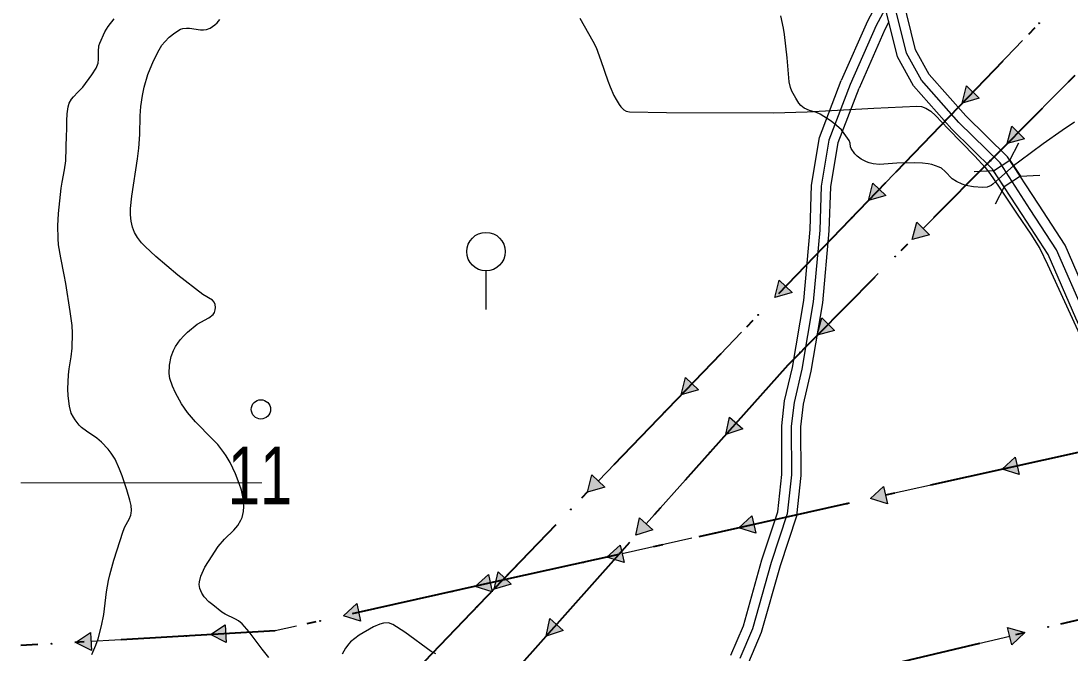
# Model space of a CAD drawing. Extents: x -64005 to -55000, y -89025 to -80000.
# Drawn here: x -64000 to -62912, y -85176 to -84521 of the extents above; entities that cross this region are included whole.
import ezdxf
from ezdxf.enums import TextEntityAlignment as Align

# ---------------------------------------------------------------- set-up
doc = ezdxf.new("R2010")
doc.units = 0
doc.header["$LTSCALE"] = 32
for name, pattern in [('DASH_DOUBLE_DOT', [9.2, 5, -1.2, 0.3, -1.2, 0.3, -1.2]), ('DOT_DASHED', [7.7, 5, -1.2, 0.3, -1.2]), ('LONG_DASHED', [7.5, 6, -1.5])]:
    doc.linetypes.add(name, pattern=pattern)
for name, color, linetype, lineweight in [('18', 7, 'Continuous', 25), ('2', 7, 'Continuous', 25), ('20', 7, 'Continuous', 25), ('24', 7, 'Continuous', 25), ('32', 7, 'Continuous', 25), ('35', 7, 'Continuous', 13), ('39', 7, 'LONG_DASHED', 25), ('52', 7, 'Continuous', 25), ('6', 7, 'Continuous', 25), ('63', 7, 'DASH_DOUBLE_DOT', 25), ('8', 7, 'Continuous', 25)]:
    doc.layers.add(name, color=color, linetype=linetype, lineweight=lineweight)
doc.layers.add('38', color=7, linetype='Continuous')

msp = doc.modelspace()

# ---------------------------------------------------------------- hatches: boundary and pattern name
at = {"layer": '18'}
for points in [[(-63005.72, -84601.15), (-63023.5, -84606.26), (-63019.04, -84588.31)], [(-62958.84, -84643.33), (-62976.69, -84648.19), (-62971.97, -84630.3)], [(-63102.86, -84701.96), (-63120.64, -84707.07), (-63116.19, -84689.12)], [(-63057.45, -84742.71), (-63075.3, -84747.56), (-63070.58, -84729.68)], [(-63200.01, -84802.77), (-63217.79, -84807.88), (-63213.33, -84789.93)], [(-63156.07, -84842.08), (-63173.92, -84846.94), (-63169.2, -84829.05)], [(-63297.15, -84903.58), (-63314.93, -84908.7), (-63310.48, -84890.74)], [(-63251.2, -84944.05), (-63268.77, -84949.85), (-63265.01, -84931.74)], [(-62964.36, -84991.49), (-62982, -84985.94), (-62968.37, -84973.43)], [(-63394.3, -85004.39), (-63412.08, -85009.51), (-63407.62, -84991.55)], [(-63101.03, -85021.85), (-63118.67, -85016.3), (-63105.04, -85003.8)], [(-63237.69, -85052.22), (-63255.34, -85046.66), (-63241.71, -85034.16)], [(-63344.36, -85048.55), (-63361.93, -85054.35), (-63358.17, -85036.24)], [(-63374.36, -85082.58), (-63392.01, -85077.02), (-63378.37, -85064.52)], [(-63511.03, -85112.94), (-63528.68, -85107.38), (-63515.04, -85094.88)], [(-63491.44, -85105.2), (-63509.22, -85110.32), (-63504.77, -85092.36)], [(-63647.7, -85143.3), (-63665.34, -85137.74), (-63651.71, -85125.24)], [(-63437.52, -85153.06), (-63455.09, -85158.86), (-63451.33, -85140.75)], [(-63926.75, -85173.71), (-63943.27, -85165.39), (-63927.81, -85155.24)], [(-63786.98, -85165.7), (-63803.5, -85157.38), (-63788.04, -85147.23)], [(-62976.32, -85149.86), (-62958.61, -85155.18), (-62972.07, -85167.87)]]:
    msp.add_hatch(color=256, dxfattribs=at).paths.add_polyline_path(points)

# ---------------------------------------------------------------- linework, layer by layer
for p, q in [((-62961.05, -84541.46), (-63012.38, -84594.73)), ((-62913.29, -84584.31), (-62965.4, -84636.82)), ((-63011.91, -84683.68), (-63064.02, -84736.19)), ((-63155.34, -84743.08), (-63206.67, -84796.35)), ((-63110.52, -84783.06), (-63162.63, -84835.57)), ((-63252.48, -84843.89), (-63303.81, -84897.16)), ((-63208.88, -84882.67), (-63258.11, -84937.89)), ((-63349.63, -84944.7), (-63400.96, -84997.97)), ((-62894.14, -84966.42), (-62966.36, -84982.46)), ((-63302.04, -84987.17), (-63351.27, -85042.4)), ((-63030.81, -84996.78), (-63103.03, -85012.83)), ((-63167.48, -85027.14), (-63239.7, -85043.19)), ((-63446.77, -85045.51), (-63498.11, -85098.78)), ((-63304.15, -85057.51), (-63376.37, -85073.55)), ((-63395.2, -85091.68), (-63444.43, -85146.9)), ((-63577.49, -85118.22), (-63649.7, -85134.27)), ((-63543.92, -85146.32), (-63595.25, -85199.59)), ((-63853.42, -85160.24), (-63927.28, -85164.48)), ((-63046.2, -85175.86), (-62974.2, -85158.86)), ((-63993.19, -85168.26), (-64000, -85168.65))]:
    msp.add_line(p, q, dxfattribs=at)
at = {"layer": '18', "linetype": 'DOT_DASHED', "lineweight": 40}
for points in [[(-55000.81, -81341.27), (-57492.65, -83191.85), (-58506.34, -83610.82), (-59176.97, -83888), (-59245.7, -83916.4), (-60498.5, -84434.2), (-61697.45, -84700.56), (-63379.7, -85074.29), (-63500.32, -85101.08), (-63736.4, -85153.53), (-64000, -85168.65)], [(-62369.26, -83445.65), (-62236.29, -83546.11), (-62227.39, -83552.83), (-62158.46, -83621.75), (-62183.05, -83848.43), (-62289.57, -83955.78), (-62419.8, -84087.01), (-63204.55, -84877.81), (-63379.7, -85074.29), (-63583.22, -85302.6), (-63848.56, -85600.24), (-64000, -85590.13)], [(-62600.64, -83578.59), (-62627.36, -83673.57), (-62637.7, -84129.6), (-62639.47, -84207.74), (-63103.07, -84688.84), (-63500.32, -85101.08), (-63677.61, -85285.06), (-63756.78, -85343.55), (-64000, -85523.25)], [(-64000, -85400.95), (-63756.78, -85343.55), (-63583.22, -85302.6), (-63160.94, -85202.94), (-62774.07, -85111.63), (-62063.05, -84888.71), (-61746.39, -84828.12), (-61731.7, -84825.31), (-61594.06, -84786.87), (-61360.14, -84721.55), (-60481.8, -84478.68), (-59562.86, -84105.04), (-59208.4, -83960.92), (-58840.52, -84105.61)]]:
    msp.add_lwpolyline(points, dxfattribs=at)
at = {"layer": '18'}
for points in [[(-63005.72, -84601.15), (-63023.5, -84606.26), (-63019.04, -84588.31)], [(-62958.84, -84643.33), (-62976.69, -84648.19), (-62971.97, -84630.3)], [(-63102.86, -84701.96), (-63120.64, -84707.07), (-63116.19, -84689.12)], [(-63057.45, -84742.71), (-63075.3, -84747.56), (-63070.58, -84729.68)], [(-63200.01, -84802.77), (-63217.79, -84807.88), (-63213.33, -84789.93)], [(-63156.07, -84842.08), (-63173.92, -84846.94), (-63169.2, -84829.05)], [(-63297.15, -84903.58), (-63314.93, -84908.7), (-63310.48, -84890.74)], [(-63251.2, -84944.05), (-63268.77, -84949.85), (-63265.01, -84931.74)], [(-62964.36, -84991.49), (-62982, -84985.94), (-62968.37, -84973.43)], [(-63394.3, -85004.39), (-63412.08, -85009.51), (-63407.62, -84991.55)], [(-63101.03, -85021.85), (-63118.67, -85016.3), (-63105.04, -85003.8)], [(-63237.69, -85052.22), (-63255.34, -85046.66), (-63241.71, -85034.16)], [(-63344.36, -85048.55), (-63361.93, -85054.35), (-63358.17, -85036.24)], [(-63374.36, -85082.58), (-63392.01, -85077.02), (-63378.37, -85064.52)], [(-63511.03, -85112.94), (-63528.68, -85107.38), (-63515.04, -85094.88)], [(-63491.44, -85105.2), (-63509.22, -85110.32), (-63504.77, -85092.36)], [(-63647.7, -85143.3), (-63665.34, -85137.74), (-63651.71, -85125.24)], [(-63437.52, -85153.06), (-63455.09, -85158.86), (-63451.33, -85140.75)], [(-63926.75, -85173.71), (-63943.27, -85165.39), (-63927.81, -85155.24)], [(-63786.98, -85165.7), (-63803.5, -85157.38), (-63788.04, -85147.23)], [(-62976.32, -85149.86), (-62958.61, -85155.18), (-62972.07, -85167.87)]]:
    msp.add_lwpolyline(points, close=True, dxfattribs=at)
for points in [[(-63058.19, -84642.27), (-63103.07, -84688.84), (-63109.52, -84695.54)], [(-63440.82, -85087.86), (-63500.32, -85101.08), (-63513.04, -85103.91)], [(-63714.15, -85148.59), (-63736.4, -85153.53), (-63787.51, -85156.46)]]:
    msp.add_lwpolyline(points, dxfattribs=at)
for centre in [(-62943.7, -84523.45), (-63040.84, -84624.26), (-62994.29, -84665.94), (-63137.99, -84725.08), (-63092.91, -84765.31), (-63235.13, -84825.89), (-63191.52, -84864.68), (-63332.28, -84926.7), (-63285.4, -84968.51), (-63006.41, -84991.36), (-63143.07, -85021.72), (-63429.42, -85027.51), (-63279.74, -85052.08), (-63378.56, -85073.02), (-63416.41, -85082.44), (-63553.08, -85112.8), (-63526.57, -85128.32), (-63689.75, -85143.17), (-62934.28, -85149.44), (-63828.46, -85158.81), (-63968.23, -85166.83)]:
    msp.add_circle(centre, 0.5, dxfattribs=at)
at = {"layer": '2'}
for points in [[(-63926.36, -85178.12), (-63922.31, -85168.46), (-63920.03, -85161.88), (-63916.34, -85148.41), (-63914.16, -85136.64), (-63911.2, -85112.91), (-63909.28, -85101.14), (-63907.97, -85095.32), (-63903.74, -85080.06), (-63894.05, -85049.98), (-63892.26, -85045.78), (-63887.87, -85037.62), (-63886.19, -85033.47), (-63885.68, -85031.35), (-63885.4, -85028.73), (-63885.73, -85023.39), (-63886.91, -85017.95), (-63890.33, -85007.14), (-63894.99, -84992.8), (-63897.62, -84985.79), (-63902.42, -84975.47), (-63906.49, -84969.08), (-63909.59, -84965.16), (-63916.36, -84957.78), (-63921.25, -84953.58), (-63932.06, -84946.49), (-63937.24, -84942.47), (-63939.61, -84940.1), (-63943.8, -84934.81), (-63945.58, -84932), (-63947.77, -84927.6), (-63949.83, -84920.54), (-63951.13, -84909.67), (-63951.41, -84902.41), (-63950.76, -84887.95), (-63950, -84881.79), (-63948.05, -84869.49), (-63947.02, -84860.24), (-63946.51, -84844.71), (-63947.02, -84836.96), (-63948.94, -84822.33), (-63953.52, -84793.19), (-63955.14, -84784.28), (-63958.75, -84766.51), (-63960.96, -84753.14), (-63961.59, -84746.67), (-63961.85, -84733.64), (-63961.11, -84720.56), (-63958.17, -84694.47), (-63957.22, -84688.15), (-63954.87, -84675.55), (-63953.63, -84666.05), (-63952.7, -84639.04), (-63952.59, -84634.19), (-63952.57, -84624.49), (-63952.18, -84617.23), (-63950.97, -84610.02), (-63949.91, -84606.44), (-63947.66, -84602.11), (-63945.64, -84599.6), (-63940.99, -84595.01), (-63935.97, -84589.68), (-63926.41, -84576.84), (-63922.03, -84570.12), (-63921.15, -84568.4), (-63920.09, -84564.73), (-63919.71, -84560.84), (-63919.7, -84552.77), (-63919.14, -84546.85), (-63918.31, -84544.04), (-63912.84, -84532.26), (-63909.48, -84526.69), (-63903.44, -84518.9)], [(-62906.81, -84625.86), (-62919.85, -84634.8), (-62939.57, -84648.49), (-62963.6, -84666.35), (-62970.21, -84671.45), (-62985.42, -84684.74), (-62991.75, -84690.4), (-62993.53, -84691.7), (-62997.69, -84693.28), (-63002.33, -84693.81), (-63011.66, -84693.15), (-63019.69, -84691.51), (-63023.66, -84690.22), (-63029.51, -84687.65), (-63033.83, -84684.61), (-63041.06, -84677.02), (-63045.04, -84673.76), (-63047.36, -84672.55), (-63054.87, -84669.94), (-63058.7, -84669.07), (-63064.53, -84668.43), (-63073.46, -84668.22), (-63091.31, -84668.43), (-63109.16, -84669.8), (-63115.7, -84669.27), (-63119.98, -84668.16), (-63122.8, -84667.12), (-63128.39, -84664.33), (-63132.6, -84661.27), (-63134.91, -84658.88), (-63138.68, -84653.34), (-63139.34, -84651.56), (-63139.87, -84647.75), (-63140.74, -84645.09), (-63145.87, -84637.59), (-63148.81, -84634.12), (-63153.79, -84629.3), (-63159.31, -84624.97), (-63170.95, -84617.62), (-63174.49, -84616.08), (-63181.98, -84613.94), (-63187.32, -84611.5), (-63190.85, -84608.58), (-63192.85, -84606.33), (-63196.25, -84601.2), (-63200.19, -84593.77), (-63201.73, -84589.97), (-63203.11, -84584.03), (-63205.17, -84559.3), (-63207.92, -84535.26), (-63208.99, -84528.7), (-63211.73, -84515.62)]]:
    msp.add_lwpolyline(points, dxfattribs=at)
at = {"layer": '20'}
for p, q in [((-62974.11, -84665.47), (-62964.88, -84647.48)), ((-62990.9, -84676.33), (-63010.96, -84677.51)), ((-62963.22, -84682.16), (-62943.04, -84680.98)), ((-62979.94, -84693.15), (-62989.11, -84711.02))]:
    msp.add_line(p, q, dxfattribs=at)
at = {"layer": '24'}
for points in [[(-63827.19, -84926.98), (-63833.32, -84918.2), (-63839.78, -84906.74), (-63842.88, -84899.69), (-63845.4, -84891.67), (-63846.11, -84886.47), (-63845.89, -84877.83), (-63844.08, -84869.13), (-63841.71, -84862.79), (-63839.68, -84858.73), (-63834.88, -84851.64), (-63831.18, -84847.49), (-63827.26, -84843.78), (-63817.16, -84835.57), (-63805.03, -84828.85), (-63800.56, -84825.38), (-63799.31, -84823.23), (-63798.57, -84820.67), (-63798.34, -84818.22), (-63798.64, -84815.2), (-63799.5, -84812.77), (-63801.36, -84810.48), (-63811.43, -84804.81), (-63837.26, -84784.66), (-63860.11, -84765.33), (-63871.26, -84755.08), (-63875.05, -84751.13), (-63879.21, -84745.7), (-63882.23, -84740.4), (-63884.4, -84734.73), (-63885.66, -84728.58), (-63886.22, -84722.13), (-63886.23, -84715.67), (-63885.12, -84702.81), (-63879.03, -84664.14), (-63877.56, -84653.07), (-63876.67, -84638.63), (-63876.29, -84619.27), (-63875.67, -84609.61), (-63874.09, -84598.39), (-63872.18, -84589.59), (-63868.26, -84576.62), (-63862.46, -84562.39), (-63856.77, -84551.05), (-63853.71, -84546.19), (-63850.91, -84542.69), (-63846.2, -84538.02), (-63840.37, -84533.5), (-63834.33, -84529.71), (-63832.18, -84528.93), (-63828.39, -84528.46), (-63825.22, -84528.63), (-63813.79, -84530.29), (-63810.6, -84530.35), (-63807.51, -84529.91), (-63803.88, -84528.37), (-63798.81, -84524.91), (-63796.47, -84522.95), (-63793.55, -84519.68)], [(-63420.34, -84518.06), (-63415.56, -84526.01), (-63406.54, -84542.16), (-63403.4, -84548.62), (-63398.23, -84561.97), (-63391.11, -84583.23), (-63388.84, -84589.28), (-63384.9, -84598.23), (-63382.61, -84602.62), (-63379.46, -84607.74), (-63377.6, -84610.16), (-63374.42, -84613.15), (-63372.04, -84614.5), (-63368.75, -84615.2)], [(-63368.75, -84615.2), (-63330.34, -84615.83), (-63219.15, -84616.37), (-63184.43, -84615.29), (-63115.04, -84611.56), (-63070.65, -84609.58), (-63065.84, -84609.91), (-63061.18, -84611.34), (-63056.09, -84614.71), (-63051.08, -84619.04), (-63038.16, -84632.78), (-63010.45, -84661.12), (-62999.64, -84673.03), (-62994.71, -84679.38), (-62985.03, -84693.3), (-62966.37, -84721.57), (-62952.37, -84742.1), (-62943.04, -84757.16), (-62934.93, -84773.55), (-62893.96, -84863.24)], [(-63742.77, -85181.04), (-63749.72, -85172.32), (-63763.13, -85154.43), (-63770.51, -85146.12), (-63774.22, -85143.12), (-63777.51, -85141.19), (-63788.1, -85136.12), (-63791.54, -85134.08), (-63801.12, -85126.66), (-63804.93, -85123.35), (-63809.93, -85118.13), (-63812.52, -85114.44), (-63814.59, -85109.6), (-63815.12, -85105.44), (-63814.93, -85102.56), (-63813.46, -85096.62), (-63809.23, -85087.5), (-63805.62, -85081.44), (-63795.4, -85065.9), (-63788.68, -85058.5), (-63779.24, -85049.07), (-63775.08, -85044.13), (-63771.76, -85038.79), (-63770.52, -85035.92), (-63769.01, -85029.72), (-63768.66, -85024.48), (-63769.34, -85016.39), (-63771.38, -85007.46), (-63773.66, -85000.66), (-63777.54, -84990.78), (-63783.13, -84978.79), (-63787.15, -84971.88), (-63789.41, -84968.54), (-63795.92, -84960.34), (-63801.53, -84954.26), (-63818.99, -84936.63), (-63827.19, -84926.98)], [(-63569.44, -85177.39), (-63574.26, -85174.72), (-63601.63, -85154.79), (-63614.35, -85146.72), (-63618.53, -85145.28), (-63624.02, -85145.45), (-63627.82, -85146.44), (-63634.13, -85149.13), (-63649.05, -85157.99), (-63653.74, -85161.34), (-63658.02, -85165), (-63659.96, -85166.98), (-63663.37, -85171.32), (-63666.6, -85177.59)]]:
    msp.add_lwpolyline(points, dxfattribs=at)
at = {"layer": '32'}
msp.add_line((-63517.54, -84780.27), (-63517.54, -84820.27), dxfattribs=at)
msp.add_circle((-63517.54, -84760.27), 20, dxfattribs=at)
at = {"layer": '35'}
msp.add_line((-64000, -85000), (-63750, -85000), dxfattribs=at)
at = {"layer": '39'}
for points in [[(-63096.11, -84494.29), (-63112.82, -84525.68), (-63139.68, -84586.8)], [(-63139.68, -84586.8), (-63161.76, -84644.52), (-63169.72, -84692.27), (-63171.31, -84737.92), (-63177.94, -84812.18), (-63189.88, -84882.22), (-63197.85, -84916.7), (-63200.77, -84941.33), (-63200.5, -84991.75), (-63205.01, -85032.08), (-63221.72, -85082.76), (-63241.08, -85151.48), (-63254.08, -85182.26)]]:
    msp.add_lwpolyline(points, dxfattribs=at)
at = {"layer": '39', "linetype": 'Continuous'}
msp.add_lwpolyline([(-62874.94, -84872.34), (-62896.31, -84825.3), (-62925.62, -84758.3), (-62952.83, -84716.42), (-62984.22, -84668.27), (-63027.12, -84626.39), (-63065.84, -84582.42), (-63081.17, -84554.57), (-63096.11, -84494.29)], dxfattribs=at)
at = {"layer": '52'}
msp.add_circle((-63751.07, -84923.81), 10, dxfattribs=at)
at = {"layer": '6'}
for points in [[(-62882.75, -84879.35), (-62905.44, -84829.37), (-62934.45, -84763.06), (-62961.22, -84721.87), (-62991.99, -84674.66), (-63034.37, -84633.28), (-63074.07, -84588.21), (-63090.56, -84558.25), (-63100.21, -84519.33), (-63107.41, -84490.28)], [(-62869.15, -84860.9), (-62887.18, -84821.23), (-62916.79, -84753.54), (-62944.44, -84710.97), (-62976.45, -84661.88), (-63019.87, -84619.5), (-63057.61, -84576.63), (-63071.78, -84550.89), (-63085.48, -84495.61)]]:
    msp.add_lwpolyline(points, dxfattribs=at)
at = {"layer": '63'}
msp.add_lwpolyline([(-62974.1, -84665.38), (-62963.16, -84682.16), (-62979.96, -84693.11), (-62990.9, -84676.33)], close=True, dxfattribs=at)
at = {"layer": '8', "linetype": 'LONG_DASHED'}
for points in [[(-63106.74, -84492.98), (-63121.82, -84521.31), (-63148.92, -84582.95)], [(-63263.41, -85178.66), (-63250.54, -85148.18), (-63231.29, -85079.84), (-63214.83, -85029.94), (-63210.5, -84991.22), (-63210.77, -84940.78), (-63207.72, -84914.98), (-63199.7, -84880.25), (-63187.86, -84810.89), (-63181.29, -84737.3), (-63179.7, -84691.46), (-63179.69, -84691.27), (-63171.46, -84641.89), (-63148.92, -84582.95)]]:
    msp.add_lwpolyline(points, dxfattribs=at)
at = {"layer": '8'}
for points in [[(-63099.54, -84522.03), (-63103.81, -84530.05), (-63130.45, -84590.64)], [(-63244.75, -85185.86), (-63231.62, -85154.79), (-63212.15, -85085.68), (-63195.19, -85034.22), (-63190.5, -84992.28), (-63190.77, -84941.89), (-63187.98, -84918.42), (-63180.07, -84884.19), (-63168.02, -84813.47), (-63161.33, -84738.54), (-63159.74, -84693.19), (-63152.06, -84647.15), (-63130.45, -84590.64)]]:
    msp.add_lwpolyline(points, dxfattribs=at)

# ---------------------------------------------------------------- texts
at = {"layer": '38', "width": 0.75}
msp.add_text('11', height=60, rotation=0.008, dxfattribs=at).set_placement((-63752.01, -85022.4), align=Align.CENTER)

doc.saveas('drawing.dxf')
